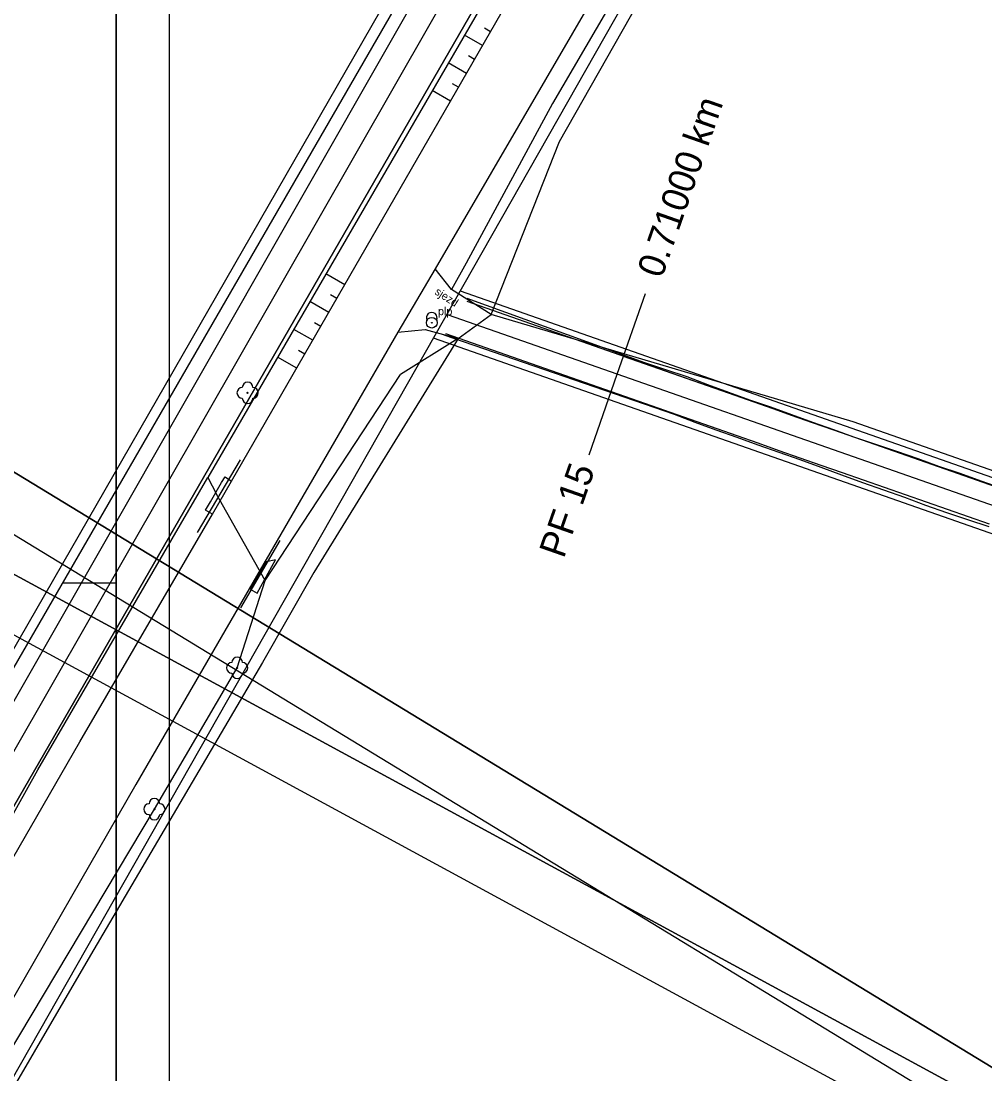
# Model space of a CAD drawing. Extents: x -555887 to -552101, y -1100251 to -1096546.
# Drawn here: x -553970.5 to -553880.4, y -1097231.6 to -1097133.2 of the extents above; entities that cross this region are included whole.
import ezdxf

# ---------------------------------------------------------------- set-up
doc = ezdxf.new("R2010")
doc.units = 0
for name, color, linetype in [('PARCELY_cesty', 7, 'Continuous'), ('PARCELY_silnice', 7, 'Continuous'), ('POLYGONY_SITUACE_PF', 7, 'Continuous'), ('POLYGONY_SITUACE_PF_POPISY', 7, 'Continuous'), ('POLYGONY_SITUACE_PO', 7, 'Continuous'), ('ram_VC6', 7, 'Continuous'), ('ROZHLED_ram_legenda_1', 7, 'Continuous'), ('ROZHLED_ram_legenda_2', 7, 'Continuous'), ('ZSST', 7, 'Continuous')]:
    doc.layers.add(name, color=color, linetype=linetype)

msp = doc.modelspace()

# ---------------------------------------------------------------- linework, layer by layer
at = {"layer": 'PARCELY_cesty'}
for points in [[(-553929.463, -1097158.381), (-553673.4, -1097248.15), (-553668.21, -1097254.17), (-553665.731, -1097263.939)], [(-553931.976, -1097162.798), (-553680.759, -1097250.766), (-553678.227, -1097251.97), (-553676.115, -1097253.602), (-553674.399, -1097255.646), (-553673.156, -1097258.009), (-553672.444, -1097260.581), (-553672.295, -1097263.246), (-553672.865, -1097266.819)]]:
    msp.add_lwpolyline(points, dxfattribs=at)
at = {"layer": 'PARCELY_silnice'}
for points in [[(-553861.3, -1097003.46), (-553858.48, -1097005.9), (-553845.75, -1096975.04), (-553836.44, -1096945.29), (-553831.55, -1096945.97), (-553834.33, -1096958.81), (-553843.04, -1096981.51), (-553856.4, -1097007.66), (-554032.65, -1097312.99), (-554038, -1097312.7), (-554039.52, -1097311.76)], [(-553831.55, -1096945.97), (-553822.14, -1096946.52), (-553820.19, -1096947.25), (-553823.19, -1096962.08), (-553832.13, -1096986.8), (-553848.04, -1097015.24), (-554028.81, -1097333.03), (-554038.74, -1097323.54), (-553856.4, -1097007.66), (-553843.04, -1096981.51), (-553834.33, -1096958.81)]]:
    msp.add_lwpolyline(points, close=True, dxfattribs=at)
at = {"layer": 'POLYGONY_SITUACE_PF'}
for p, q in [((-553914.764, -1097166.176), (-553912.12, -1097158.626)), ((-553917.408, -1097173.727), (-553914.764, -1097166.176))]:
    msp.add_line(p, q, dxfattribs=at)
at = {"layer": 'POLYGONY_SITUACE_PO'}
for p, q in [((-553804.075, -1097203.082), (-553928.817, -1097159.401)), ((-553912.19, -1097165.128), (-553928.801, -1097159.093)), ((-553679.807, -1097248.45), (-553930.542, -1097160.651)), ((-553930.975, -1097162.492), (-553909.452, -1097169.917)), ((-553903.545, -1097171.959), (-553930.811, -1097162.412)), ((-553912.219, -1097165.213), (-553914.186, -1097164.525)), ((-553910.253, -1097165.902), (-553912.219, -1097165.213)), ((-553910.214, -1097165.788), (-553912.19, -1097165.128)), ((-553908.287, -1097166.59), (-553910.253, -1097165.902)), ((-553908.229, -1097166.424), (-553910.214, -1097165.788)), ((-553906.281, -1097167.166), (-553908.229, -1097166.424)), ((-553906.321, -1097167.279), (-553908.287, -1097166.59)), ((-553904.354, -1097167.967), (-553906.321, -1097167.279)), ((-553904.335, -1097167.911), (-553906.281, -1097167.166)), ((-553913.376, -1097168.517), (-553915.342, -1097167.828)), ((-553902.388, -1097168.656), (-553904.354, -1097167.967)), ((-553902.37, -1097168.605), (-553904.335, -1097167.911)), ((-553911.41, -1097169.205), (-553913.376, -1097168.517)), ((-553909.444, -1097169.894), (-553911.41, -1097169.205)), ((-553900.422, -1097169.344), (-553902.388, -1097168.656)), ((-553900.392, -1097169.259), (-553902.37, -1097168.605)), ((-553898.456, -1097170.033), (-553900.422, -1097169.344)), ((-553898.441, -1097169.99), (-553900.392, -1097169.259)), ((-553909.452, -1097169.917), (-553907.506, -1097170.663)), ((-553907.477, -1097170.582), (-553909.444, -1097169.894)), ((-553896.489, -1097170.721), (-553898.456, -1097170.033)), ((-553896.485, -1097170.709), (-553898.441, -1097169.99)), ((-553907.506, -1097170.663), (-553905.547, -1097171.374)), ((-553905.511, -1097171.271), (-553907.477, -1097170.582)), ((-553905.547, -1097171.374), (-553903.582, -1097172.066)), ((-553903.545, -1097171.959), (-553905.511, -1097171.271)), ((-553894.523, -1097171.41), (-553896.489, -1097170.721)), ((-553894.512, -1097171.379), (-553896.485, -1097170.709)), ((-553892.557, -1097172.098), (-553894.523, -1097171.41)), ((-553892.648, -1097172.066), (-553894.512, -1097171.379)), ((-553903.582, -1097172.066), (-553901.626, -1097172.784)), ((-553901.579, -1097172.648), (-553903.545, -1097171.959)), ((-553901.579, -1097172.648), (-553903.545, -1097171.959)), ((-553892.556, -1097172.097), (-553892.648, -1097172.066)), ((-553890.591, -1097172.787), (-553892.557, -1097172.098)), ((-553890.58, -1097172.756), (-553892.556, -1097172.097)), ((-553901.626, -1097172.784), (-553899.661, -1097173.475)), ((-553899.612, -1097173.336), (-553901.579, -1097172.648)), ((-553899.612, -1097173.336), (-553901.579, -1097172.648)), ((-553897.646, -1097174.025), (-553899.612, -1097173.336)), ((-553897.646, -1097174.025), (-553899.612, -1097173.336)), ((-553888.624, -1097173.475), (-553890.591, -1097172.787)), ((-553888.603, -1097173.414), (-553890.58, -1097172.756)), ((-553886.636, -1097174.102), (-553888.603, -1097173.414)), ((-553899.661, -1097173.475), (-553897.689, -1097174.147)), ((-553897.689, -1097174.147), (-553895.733, -1097174.866)), ((-553895.68, -1097174.713), (-553897.646, -1097174.025)), ((-553895.68, -1097174.713), (-553897.646, -1097174.025)), ((-553886.658, -1097174.164), (-553888.624, -1097173.475)), ((-553884.692, -1097174.852), (-553886.658, -1097174.164)), ((-553884.674, -1097174.802), (-553886.636, -1097174.102)), ((-553895.733, -1097174.866), (-553893.781, -1097175.593)), ((-553893.713, -1097175.402), (-553895.68, -1097174.713)), ((-553893.713, -1097175.402), (-553895.68, -1097174.713)), ((-553882.725, -1097175.541), (-553884.692, -1097174.852)), ((-553882.702, -1097175.473), (-553884.674, -1097174.802)), ((-553893.781, -1097175.593), (-553891.822, -1097176.303)), ((-553891.747, -1097176.09), (-553893.713, -1097175.402)), ((-553891.747, -1097176.09), (-553893.713, -1097175.402)), ((-553891.822, -1097176.303), (-553889.852, -1097176.983)), ((-553889.781, -1097176.779), (-553891.747, -1097176.09)), ((-553889.781, -1097176.779), (-553891.747, -1097176.09)), ((-553880.759, -1097176.229), (-553882.725, -1097175.541)), ((-553880.741, -1097176.179), (-553882.702, -1097175.473)), ((-553878.793, -1097176.918), (-553880.759, -1097176.229)), ((-553878.776, -1097176.871), (-553880.741, -1097176.179)), ((-553889.852, -1097176.983), (-553887.891, -1097177.684)), ((-553887.815, -1097177.467), (-553889.781, -1097176.779)), ((-553887.815, -1097177.467), (-553889.781, -1097176.779)), ((-553887.891, -1097177.684), (-553885.948, -1097178.441)), ((-553885.848, -1097178.156), (-553887.815, -1097177.467)), ((-553885.848, -1097178.156), (-553887.815, -1097177.467)), ((-553883.882, -1097178.844), (-553885.848, -1097178.156)), ((-553883.882, -1097178.844), (-553885.848, -1097178.156)), ((-553885.948, -1097178.441), (-553883.972, -1097179.102)), ((-553883.972, -1097179.102), (-553881.997, -1097179.766)), ((-553881.916, -1097179.533), (-553883.882, -1097178.844)), ((-553881.916, -1097179.533), (-553883.882, -1097178.844)), ((-553881.997, -1097179.766), (-553880.023, -1097180.43)), ((-553879.95, -1097180.221), (-553881.916, -1097179.533)), ((-553879.95, -1097180.221), (-553881.916, -1097179.533))]:
    msp.add_line(p, q, dxfattribs=at)
at = {"layer": 'ram_VC6'}
msp.add_line((-553961.64, -1097185.72), (-553966.64, -1097185.72), dxfattribs=at)
for points in [[(-553956.64, -1096765.72), (-554313.64, -1096765.72), (-554313.64, -1097395.72), (-553956.64, -1097395.72)], [(-553961.64, -1096770.72), (-554308.64, -1096770.72), (-554308.64, -1097390.72), (-553961.64, -1097390.72)]]:
    msp.add_lwpolyline(points, close=True, dxfattribs=at)
for points in [[(-553956.64, -1096765.72), (-554313.64, -1096765.72), (-554313.64, -1097395.72), (-553956.64, -1097395.72), (-553956.64, -1096765.72)], [(-553956.64, -1096765.72), (-554313.64, -1096765.72), (-554313.64, -1097395.72), (-553956.64, -1097395.72), (-553956.64, -1096765.72)], [(-553961.64, -1097390.72), (-554308.64, -1097390.72), (-554308.64, -1096770.72), (-553961.64, -1096770.72), (-553961.64, -1097390.72)], [(-553961.64, -1097185.72), (-553961.64, -1097390.72), (-554308.64, -1097390.72), (-554308.64, -1096770.72), (-553961.64, -1096770.72), (-553961.64, -1096975.72), (-553961.64, -1097185.72)]]:
    msp.add_lwpolyline(points, dxfattribs=at)
at = {"layer": 'ROZHLED_ram_legenda_1'}
msp.add_lwpolyline([(-554022.385, -1097495.033), (-554206.959, -1097394.87), (-554065.3, -1097133.83), (-553880.726, -1097233.993)], close=True, dxfattribs=at)
msp.add_lwpolyline([(-554022.385, -1097495.033), (-554206.959, -1097394.87), (-554065.3, -1097133.83), (-553880.726, -1097233.993)], close=True, dxfattribs=at)
for points in [[(-553880.726, -1097233.993), (-554065.3, -1097133.83), (-554206.959, -1097394.87), (-554022.385, -1097495.033), (-553880.726, -1097233.993)], [(-554200.18, -1097392.86), (-554063.29, -1097140.609), (-553887.506, -1097236.003), (-554024.395, -1097488.253), (-554200.18, -1097392.86)], [(-554200.18, -1097392.86), (-554063.29, -1097140.609), (-553887.506, -1097236.003), (-554024.395, -1097488.253), (-554200.18, -1097392.86)]]:
    msp.add_lwpolyline(points, dxfattribs=at)
at = {"layer": 'ROZHLED_ram_legenda_2'}
msp.add_lwpolyline([(-553994.764, -1097161.002), (-553815.355, -1097270.146), (-553969.717, -1097523.882), (-554149.126, -1097414.737)], close=True, dxfattribs=at)
msp.add_lwpolyline([(-553994.764, -1097161.002), (-553815.355, -1097270.146), (-553969.717, -1097523.882), (-554149.126, -1097414.737)], close=True, dxfattribs=at)
for points in [[(-554149.126, -1097414.737), (-553969.717, -1097523.882), (-553815.355, -1097270.146), (-553994.764, -1097161.002), (-554149.126, -1097414.737)], [(-553822.226, -1097271.819), (-553971.39, -1097517.011), (-554142.255, -1097413.064), (-553993.091, -1097167.872), (-553822.226, -1097271.819)], [(-553822.226, -1097271.819), (-553971.39, -1097517.011), (-554142.255, -1097413.064), (-553993.091, -1097167.872), (-553822.226, -1097271.819)]]:
    msp.add_lwpolyline(points, dxfattribs=at)
at = {"layer": 'ZSST'}
for p, q in [((-553926.629, -1097134.161), (-553927.191, -1097133.837)), ((-553927.378, -1097135.461), (-553929.069, -1097134.486)), ((-553928.127, -1097136.76), (-553928.691, -1097136.435)), ((-553928.876, -1097138.06), (-553930.575, -1097137.081)), ((-553930.373, -1097140.66), (-553932.08, -1097139.676)), ((-553929.624, -1097139.36), (-553930.191, -1097139.033)), ((-553940.257, -1097157.819), (-553942.015, -1097156.806)), ((-553941.755, -1097160.418), (-553943.521, -1097159.401)), ((-553941.006, -1097159.118), (-553941.593, -1097158.78)), ((-553942.503, -1097161.718), (-553943.093, -1097161.379)), ((-553943.252, -1097163.018), (-553945.026, -1097161.996)), ((-553929.66, -1097162.86), (-553943.15, -1097184.71)), ((-553929.66, -1097162.86), (-553935.03, -1097166.22)), ((-553944.001, -1097164.318), (-553944.593, -1097163.977)), ((-553944.75, -1097165.617), (-553946.531, -1097164.591)), ((-553947.7, -1097185.48), (-553935.03, -1097166.22)), ((-553954.03, -1097181), (-553950.01, -1097174.2)), ((-553968.97, -1097203.17), (-553953.05, -1097175.83)), ((-553947.7, -1097185.48), (-553952.25, -1097177.39)), ((-553946.34, -1097181.73), (-553950, -1097188.03)), ((-553978.54, -1097220.29), (-553968.97, -1097203.17))]:
    msp.add_line(p, q, dxfattribs=at)
for points in [[(-554042.48, -1097312.42), (-554035.18, -1097301.12), (-554020.35, -1097276.71), (-554001.25, -1097243.62), (-553975.55, -1097199.35), (-553927.26, -1097115.35), (-553902.63, -1097072.54), (-553878.35, -1097029.34), (-553858.27, -1096995.26), (-553851.54, -1096982.63), (-553845.34, -1096967.24), (-553838.37, -1096941.91), (-553834.5, -1096923.22)], [(-553831.64, -1096923.82), (-553835.69, -1096943.09), (-553842.4, -1096966.86), (-553850.34, -1096985.69), (-553856.05, -1096996.17), (-553876.09, -1097031.09), (-553900.82, -1097073.95), (-553925.65, -1097117.01), (-553973.36, -1097200.46), (-553998.81, -1097244.48), (-554018.03, -1097278.18), (-554032.06, -1097302.7), (-554039.09, -1097314.61), (-554042.48, -1097312.42), (-554044.85, -1097316.43), (-554041.28, -1097318.43), (-554043.66, -1097322.75), (-554050.44, -1097334.64), (-554051.91, -1097337.2)], [(-553818.18, -1096926.71), (-553821.78, -1096945.09), (-553822.5, -1096948.29), (-553824.54, -1096956.94), (-553827.64, -1096967.4), (-553833.07, -1096981.13), (-553839.89, -1096995.89), (-553855.52, -1097024.97), (-553869.86, -1097050.06), (-553885.29, -1097076.39), (-553900.2, -1097101.88), (-553913.69, -1097125.22), (-553931.8, -1097156.33), (-553935.29, -1097162.25), (-553959.78, -1097204.54), (-553977.15, -1097234.71), (-553995.37, -1097266.5), (-554014.37, -1097299.01), (-554027.49, -1097321.67), (-554032.14, -1097329.71), (-554046.52, -1097353.89)], [(-553926.55, -1097160.61), (-553920.16, -1097144.42), (-553903.88, -1097115.75), (-553879.8, -1097073.43), (-553859.49, -1097037.54), (-553840.37, -1097003.2), (-553826.98, -1096978.96), (-553821.46, -1096968.7), (-553816.98, -1096958.25), (-553815.51, -1096947.8)], [(-553820.09, -1096961.14), (-553823.34, -1096968.2), (-553828.7, -1096977.66), (-553841.08, -1097002.44), (-553860.54, -1097036.95), (-553881.31, -1097072.81), (-553905.68, -1097114.94), (-553920.81, -1097140.89), (-553928.91, -1097155.8), (-553930.27, -1097158.26)], [(-553924.99, -1097120.68), (-553971.37, -1097201.71), (-553996.85, -1097245.92), (-554016.03, -1097279.48), (-554030.15, -1097304.02), (-554037.01, -1097315.92), (-554034.1, -1097317.54), (-554032.86, -1097317.31), (-554031.97, -1097316.4), (-554020.07, -1097295.69), (-554001.07, -1097262.91), (-553982.69, -1097231.14), (-553965.04, -1097200.55), (-553952.61, -1097179.27), (-553950.84, -1097176.19), (-553920.35, -1097123.26)], [(-553924.99, -1097120.68), (-553924.16, -1097124.02), (-553925.51, -1097128.35), (-553953.05, -1097175.83), (-553952.25, -1097177.39)], [(-553935.29, -1097162.25), (-553932.73, -1097162.01), (-553929.66, -1097162.86), (-553926.55, -1097160.61), (-553930.27, -1097158.26), (-553931.8, -1097156.33)], [(-553600.1, -1097268.75), (-553657.15, -1097250.01), (-553728.97, -1097225.8), (-553769.71, -1097212.97), (-553838.99, -1097189.46), (-553892.69, -1097170.63), (-553926.55, -1097160.61)], [(-553952.82, -1097178.13), (-553951.79, -1097176.3), (-553951.45, -1097175.79), (-553950.84, -1097176.19)], [(-553952.61, -1097179.27), (-553953.29, -1097178.91), (-553952.82, -1097178.13)], [(-553943.15, -1097184.71), (-553947.95, -1097193.13), (-553964.05, -1097220.5), (-553982.17, -1097251.56), (-553993.46, -1097272.56)], [(-553971.79, -1097229.88), (-553958.06, -1097206.85), (-553950.32, -1097193.64), (-553947.7, -1097185.48)]]:
    msp.add_lwpolyline(points, dxfattribs=at)
msp.add_lwpolyline([(-553949.09, -1097186.29), (-553948.45, -1097186.65), (-553946.74, -1097183.55), (-553947.58, -1097183.73)], close=True, dxfattribs=at)
for centre, radius in [((-553932.117, -1097161.371), 0.5), ((-553932.117, -1097161.371), 0.0327), ((-553949.34, -1097167.93), 0.05), ((-553950.32, -1097193.64), 0.05), ((-553958.06, -1097206.85), 0.05)]:
    msp.add_circle(centre, radius, dxfattribs=at)
for centre, start, end in [((-553932.117, -1097160.908), 331.78911, 208.78435), ((-553949.84, -1097167.93), 90, 270), ((-553949.34, -1097167.43), 0, 180), ((-553948.84, -1097167.93), 270, 90), ((-553949.34, -1097168.43), 180, 0), ((-553950.32, -1097193.14), 0, 180), ((-553950.82, -1097193.64), 90, 270), ((-553949.82, -1097193.64), 270, 90), ((-553950.32, -1097194.14), 180, 0), ((-553958.06, -1097206.35), 0, 180), ((-553958.56, -1097206.85), 90, 270), ((-553957.56, -1097206.85), 270, 90), ((-553958.06, -1097207.35), 180, 0)]:
    msp.add_arc(centre, 0.5, start, end, dxfattribs=at)

# ---------------------------------------------------------------- texts
at = {"layer": 'POLYGONY_SITUACE_PF_POPISY'}
for s, p in [('0.71000 km', (-553910.597, -1097157.302)), ('PF 15', (-553919.769, -1097183.495))]:
    msp.add_text(s, height=2.5, rotation=70.70152, dxfattribs=at).set_placement(p)
at = {"layer": 'ZSST'}
msp.add_text('sjezd', height=0.75, rotation=327.04431, dxfattribs=at).set_placement((-553931.908, -1097158.651))
msp.add_text('plp', height=0.75, dxfattribs=at).set_placement((-553931.53, -1097160.669))

doc.saveas('drawing.dxf')
